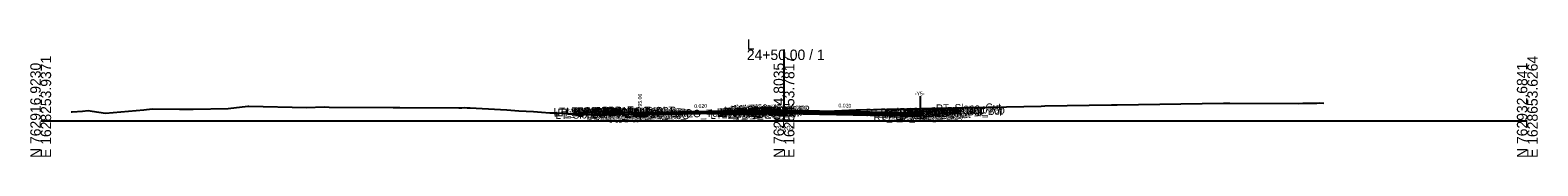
# Model space of a CAD drawing. Extents: x -26 to 4403, y -510 to 9556.
# Drawn here: x 997.2 to 1402.8, y 4490.3 to 4522 of the extents above; entities that cross this region are included whole.
import ezdxf

# ---------------------------------------------------------------- set-up
doc = ezdxf.new("R2010")
doc.units = 0
for name, color, linetype in [('Default', 7, 'Continuous'), ('Exist CMT Pavement', 7, 'Continuous'), ('Exist Cross Section Cell', 7, 'Continuous'), ('Exist XS Center Line Elevation Label', 7, 'Continuous'), ('Exist XS Ground Line', 7, 'Continuous'), ('Prop CMT Conc Surface', 7, 'Continuous'), ('Prop CMT Concrete Structures', 7, 'Continuous'), ('Prop CMT Pvmt Course 1', 7, 'Continuous'), ('Prop CMT Pvmt Course 1 CG', 7, 'Continuous'), ('Prop CMT Pvmt Course 1 Wedge', 7, 'Continuous'), ('Prop CMT Pvmt Course 2', 7, 'Continuous'), ('Prop CMT Pvmt Course 2 Wedge', 7, 'Continuous'), ('Prop CMT Pvmt Course 3', 7, 'Continuous'), ('Prop CMT Pvmt Course 3 Wedge', 7, 'Continuous'), ('Prop CMT Pvmt Surface', 7, 'Continuous'), ('Prop CMT Pvmt Wedge Surface 1', 7, 'Continuous'), ('Prop CMT Pvmt Wedge Surface 2', 7, 'Continuous'), ('Prop CMT Pvmt Wedge Surface 3', 7, 'Continuous'), ('Prop CMT Shear Line', 7, 'Continuous'), ('Prop CMT Subgrade Earthwork', 7, 'Continuous'), ('Prop XS Hydro Elevations', 7, 'Continuous'), ('Prop XS SE Text', 7, 'Continuous'), ('Scratch_Level_0', 7, 'Continuous')]:
    doc.layers.add(name, color=color, linetype=linetype)

msp = doc.modelspace()

# ---------------------------------------------------------------- linework, layer by layer
at = {"layer": 'Exist CMT Pavement'}
msp.add_lwpolyline([(1163.26, 4501.92), (1164.8, 4501.97), (1171.33, 4502.1), (1187.17, 4501.8), (1192, 4501.75)], dxfattribs=at)
at = {"layer": 'Exist Cross Section Cell'}
for p, q in [((1200, 4500), (1200, 4519.15)), ((1000, 4500), (1200, 4500)), ((1200, 4500), (1400, 4500))]:
    msp.add_line(p, q, dxfattribs=at)
at = {"layer": 'Exist XS Ground Line'}
msp.add_lwpolyline([(1008.18, 4502.4), (1008.49, 4502.41), (1011.23, 4502.63), (1012.8, 4502.75), (1013.86, 4502.58), (1017.47, 4502.04), (1027.71, 4502.96), (1030.01, 4503.17), (1037.35, 4503.15), (1041, 4503.16), (1050.42, 4503.33), (1055.71, 4503.89), (1056.03, 4503.89), (1071.5, 4503.54), (1076.31, 4503.74), (1077.61, 4503.65), (1094.85, 4503.6), (1095.34, 4503.6), (1096.65, 4503.59), (1112.49, 4503.52), (1113.32, 4503.52), (1114.01, 4503.53), (1114.71, 4503.46), (1115.54, 4503.44), (1123.71, 4503.03), (1125.38, 4502.99), (1128.66, 4502.66), (1132.64, 4502.47), (1134.75, 4502.3), (1137.01, 4502.16), (1138.89, 4502.17), (1143.69, 4501.9), (1146.02, 4501.9), (1148.59, 4501.59), (1149.36, 4501.47), (1164.8, 4501.97), (1171.33, 4502.1), (1187.17, 4501.8), (1193.05, 4501.74), (1193.4, 4501.75), (1194.22, 4501.79), (1195.2, 4501.83), (1200, 4502.04), (1219.45, 4502.91), (1220.62, 4502.93), (1238.54, 4503.31), (1241.19, 4503.37), (1269.18, 4503.97), (1270.19, 4503.99), (1288.15, 4504.26), (1289.61, 4504.27), (1318.28, 4504.7), (1319.07, 4504.71), (1319.98, 4504.72), (1338.5, 4504.67), (1339.62, 4504.7), (1340.53, 4504.72), (1343.37, 4504.73), (1344.14, 4504.79), (1345.26, 4504.75)], dxfattribs=at)
at = {"layer": 'Prop CMT Conc Surface'}
msp.add_lwpolyline([(1163.25, 4502.18), (1161.25, 4502.06)], dxfattribs=at)
at = {"layer": 'Prop CMT Concrete Structures'}
for p, q in [((1146.25, 4502.24), (1143.99, 4501.9)), ((1151.25, 4502.44), (1146.25, 4502.24)), ((1156.75, 4502.33), (1151.25, 4502.44)), ((1160.75, 4502.17), (1156.75, 4502.33)), ((1161.25, 4502.06), (1160.75, 4502.17))]:
    msp.add_line(p, q, dxfattribs=at)
for points in [[(1196, 4502.99), (1195.99, 4503.16), (1195.24, 4503.41), (1194, 4503.43), (1192.76, 4503.17), (1192.01, 4502.92), (1192, 4502.75)], [(1151.75, 4502.09), (1151.75, 4502.43)], [(1156.75, 4501.99), (1151.75, 4502.09)], [(1156.75, 4502.33), (1156.75, 4501.99)], [(1160.75, 4502.17), (1160.75, 4501.54), (1163.25, 4501.59)], [(1163.25, 4502.18), (1161.25, 4502.06)], [(1163.25, 4501.59), (1163.25, 4502.18)], [(1192, 4502.75), (1196, 4502.99)]]:
    msp.add_lwpolyline(points, dxfattribs=at)
at = {"layer": 'Prop CMT Pvmt Course 1'}
for points in [[(1192, 4502.75), (1163.25, 4502.18)], [(1163.25, 4502.05), (1192, 4502.63)], [(1163.25, 4502.18), (1163.25, 4501.93), (1163.25, 4501.93), (1163.25, 4502.05)], [(1192, 4502.75), (1196, 4502.99)], [(1192, 4502.5), (1192, 4502.75)], [(1192, 4502.5), (1192, 4502.75)], [(1196, 4502.74), (1192, 4502.5)], [(1192, 4502.63), (1192, 4502.5), (1192, 4502.5)], [(1196, 4502.99), (1196, 4502.74)], [(1196, 4502.99), (1236.75, 4502.18)], [(1196, 4502.74), (1196, 4502.99)], [(1236.75, 4501.93), (1196, 4502.74)], [(1236.75, 4502.18), (1236.75, 4501.93)]]:
    msp.add_lwpolyline(points, dxfattribs=at)
msp.add_lwpolyline([(1196, 4502.74), (1196, 4502.87), (1196, 4502.87), (1196, 4502.74)], close=True, dxfattribs=at)
at = {"layer": 'Prop CMT Pvmt Course 1 CG'}
for points in [[(1163.25, 4501.59), (1160.25, 4501.53), (1159.91, 4501.19)], [(1159.91, 4501.19), (1163.25, 4501.26)], [(1163.25, 4501.26), (1163.25, 4501.59)], [(1236.75, 4501.26), (1236.75, 4501.59)]]:
    msp.add_lwpolyline(points, dxfattribs=at)
at = {"layer": 'Prop CMT Pvmt Course 1 Wedge'}
for points in [[(1163.25, 4502.05), (1164.8, 4502.08), (1171.33, 4502.21), (1187.17, 4502.53), (1192, 4502.63)], [(1192, 4502.5), (1187.17, 4502.4), (1171.65, 4502.09), (1171.33, 4502.1), (1164.8, 4501.97), (1164.02, 4501.94), (1163.25, 4501.93)], [(1163.25, 4501.93), (1163.25, 4502.05)], [(1192, 4502.63), (1192, 4502.5)]]:
    msp.add_lwpolyline(points, dxfattribs=at)
at = {"layer": 'Prop CMT Pvmt Course 2'}
for points in [[(1163.25, 4501.59), (1163.25, 4501.59), (1163.25, 4501.93), (1163.25, 4501.93)], [(1163.25, 4501.93), (1163.25, 4501.59)], [(1192, 4502.5), (1196, 4502.74)], [(1192, 4502.17), (1192, 4502.5)], [(1196, 4502.41), (1192, 4502.17)], [(1196, 4502.74), (1196, 4502.41)], [(1196, 4502.41), (1196, 4502.74)], [(1196, 4502.74), (1236.75, 4501.93)], [(1236.75, 4501.59), (1196, 4502.41)], [(1236.75, 4501.93), (1236.75, 4501.59)]]:
    msp.add_lwpolyline(points, dxfattribs=at)
at = {"layer": 'Prop CMT Pvmt Course 2 Wedge'}
for points in [[(1163.25, 4501.93), (1164.02, 4501.94)], [(1164.02, 4501.94), (1163.25, 4501.92)], [(1163.25, 4501.92), (1163.25, 4501.93)], [(1171.65, 4502.09), (1187.17, 4502.4)], [(1192, 4502.17), (1187.17, 4502.07), (1180.18, 4501.93), (1171.65, 4502.09)], [(1187.17, 4502.4), (1192, 4502.5)], [(1192, 4502.5), (1192, 4502.17)]]:
    msp.add_lwpolyline(points, dxfattribs=at)
at = {"layer": 'Prop CMT Pvmt Course 3'}
for points in [[(1163.25, 4501.59), (1163.25, 4501.59), (1163.25, 4501.26), (1163.25, 4501.26)], [(1163.25, 4501.26), (1163.25, 4501.59)], [(1192, 4502.17), (1196, 4502.41)], [(1192, 4501.83), (1192, 4502.17)], [(1196, 4502.07), (1192, 4501.83)], [(1196, 4502.41), (1196, 4502.07)], [(1196, 4502.41), (1236.75, 4501.59)], [(1196, 4502.07), (1196, 4502.41)], [(1236.75, 4501.26), (1196, 4502.07)], [(1236.75, 4501.59), (1236.75, 4501.26)]]:
    msp.add_lwpolyline(points, dxfattribs=at)
at = {"layer": 'Prop CMT Pvmt Course 3 Wedge'}
for points in [[(1180.19, 4501.93), (1187.17, 4502.07)], [(1192, 4501.73), (1187.17, 4501.8), (1180.19, 4501.93)], [(1187.17, 4502.07), (1192, 4502.17)], [(1192, 4502.17), (1192, 4501.73)]]:
    msp.add_lwpolyline(points, dxfattribs=at)
at = {"layer": 'Prop CMT Pvmt Surface'}
for points in [[(1192, 4502.75), (1163.25, 4502.18)], [(1192, 4502.75), (1196, 4502.99)], [(1196, 4502.99), (1236.75, 4502.18)]]:
    msp.add_lwpolyline(points, dxfattribs=at)
at = {"layer": 'Prop CMT Pvmt Wedge Surface 1'}
for points in [[(1192, 4502.63), (1163.25, 4502.05)], [(1163.25, 4501.93), (1163.25, 4502.18)], [(1163.25, 4502.05), (1163.25, 4501.93), (1163.25, 4501.93)], [(1192, 4502.75), (1192, 4502.5), (1192, 4502.5), (1192, 4502.63)]]:
    msp.add_lwpolyline(points, dxfattribs=at)
at = {"layer": 'Prop CMT Pvmt Wedge Surface 2'}
for points in [[(1192, 4502.5), (1163.25, 4501.93)], [(1163.25, 4501.93), (1163.25, 4502.18)], [(1192, 4502.75), (1192, 4502.5)]]:
    msp.add_lwpolyline(points, dxfattribs=at)
at = {"layer": 'Prop CMT Pvmt Wedge Surface 3'}
for points in [[(1163.25, 4501.59), (1163.25, 4502.18)], [(1192, 4502.17), (1163.25, 4501.59)], [(1192, 4502.75), (1192, 4502.17)]]:
    msp.add_lwpolyline(points, dxfattribs=at)
at = {"layer": 'Prop CMT Shear Line'}
msp.add_line((1236.75, 4500.37), (1236.75, 4506.64), dxfattribs=at)
at = {"layer": 'Prop CMT Subgrade Earthwork'}
for p, q in [((1236.75, 4501.26), (1236.75, 4503.27)), ((1192, 4501.75), (1192, 4501.83))]:
    msp.add_line(p, q, dxfattribs=at)
for points in [[(1163.25, 4501.26), (1159.91, 4501.19), (1158.86, 4502.24)], [(1163.25, 4501.26), (1163.26, 4501.92)], [(1163.25, 4501.26), (1163.25, 4501.26)], [(1192, 4501.83), (1196, 4502.07)], [(1196, 4502.07), (1236.75, 4501.26)]]:
    msp.add_lwpolyline(points, dxfattribs=at)

# ---------------------------------------------------------------- texts
at = {"layer": 'Default'}
msp.add_text('-', height=0.0001, dxfattribs=at).set_placement((1000, 4500))
at = {"layer": 'Exist Cross Section Cell'}
for s, p in [('24+50.00 / 1', (1190, 4516.35)), ('L', (1190, 4519.15))]:
    msp.add_text(s, height=2.8, dxfattribs=at).set_placement(p)
for s, p in [('N 762916.9230', (1000, 4490)), ('E 1628253.9371', (1002.8, 4490)), ('N 762924.8035', (1200, 4490)), ('E 1628453.7817', (1202.8, 4490)), ('N 762932.6841', (1400, 4490)), ('E 1628653.6264', (1402.8, 4490))]:
    msp.add_text(s, height=2.8, rotation=90, dxfattribs=at).set_placement(p)
at = {"layer": 'Exist XS Center Line Elevation Label'}
msp.add_text('795.04', height=1.2, dxfattribs=at).set_placement((1197.48, 4497.44))
at = {"layer": 'Prop XS Hydro Elevations'}
for s, rotation, p in [('-Y5-', 360, (1235.23, 4506.81)), ('795.06', 90, (1161.75, 4503.06))]:
    msp.add_text(s, height=1, rotation=rotation, dxfattribs=at).set_placement(p)
at = {"layer": 'Prop XS SE Text'}
for s, rotation, p in [('15.00%', 8.5308, (1141.27, 4501.84)), ('4.00%', 2.2906, (1146.99, 4502.49)), ('2.00%', 358.8542, (1152.4, 4502.61)), ('4.00%', 357.7094, (1156.62, 4502.64)), ('0.020', 1.1458, (1175.86, 4503.43)), ('0.020', 358.8542, (1214.65, 4503.62))]:
    msp.add_text(s, height=1, rotation=rotation, dxfattribs=at).set_placement(p)
at = {"layer": 'Scratch_Level_0'}
for s, p in [('LT_SDWK_Out_Top', (1138.01, 4501.47)), ('LT_SDWK_Out_Bot', (1138.04, 4501.14)), ('LT_Sub_Trench_Out_DLT', (1139.09, 4501.21)), ('LT_CSLP_Pnt', (1141.45, 4501.55)), ('24+50.00', (1143.18, 4501.17)), ('LT_SDWK_In_Top', (1144.63, 4501.4)), ('LT_SDWK_In_Bot', (1144.66, 4501.07)), ('24+50.00', (1144.76, 4501.61)), ('LT_PV_Sub_Tie_Out', (1148.23, 4500.62)), ('LT_CG_Top_Face', (1148.53, 4501.3)), ('LT_CG_Top_BOC', (1149.05, 4501.32)), ('LT_CG_Top_Gut', (1149.51, 4500.82)), ('LT_PV_OEEOP_EG', (1150.82, 4500.67)), ('LT_PV2_OEEOP', (1152.58, 4500.71)), ('LT_PV1_OEEOP', (1153.15, 4500.85)), ('LT_PV2_OEOT', (1153.44, 4500.73)), ('24+50.00', (1153.66, 4501.43)), ('LT_PV1_OEOT', (1154.01, 4500.99)), ('24+50.00', (1155.31, 4500.97)), ('LT_PV_EG_TestPt', (1164.06, 4500.71)), ('LT_PV2_IEEOP', (1181.97, 4501.3)), ('LT_PV3_IEEOP', (1181.97, 4500.97)), ('LT_PV1_IEEOP', (1182.54, 4501.44)), ('LT_PV2_PGL1', (1182.9, 4501.32)), ('LT_PV3_PGL1', (1182.9, 4500.98)), ('LT_PV2_PGL', (1183.23, 4501.33)), ('LT_PV3_PGL', (1183.23, 4500.99)), ('LT_PV1_PGL', (1183.8, 4501.59)), ('MI_Face In', (1183.92, 4501.76)), ('RT_Sub_OEEOP', (1185.19, 4500.86)), ('24+50.00', (1185.27, 4501.7)), ('RT_PV2_OEEOP', (1185.28, 4501.53)), ('RT_PV3_OEEOP', (1185.28, 4501.19)), ('24+50.00', (1185.68, 4501.92)), ('MI_Top In', (1185.63, 4502.02)), ('RT_PV1_OEEOP', (1185.85, 4501.66)), ('RT_PV2_IEEOP', (1185.93, 4501.54)), ('MI_Face Out', (1186.28, 4501.96)), ('MI_Top Out', (1186.49, 4502.23)), ('RT_PV1_IEEOP', (1186.49, 4501.68)), ('RT_PV2_PGL1', (1186.86, 4501.56)), ('RT_PV3_PGL1', (1186.86, 4501.22)), ('MI_Crown', (1187.09, 4502.29)), ('RT_PV2_PGL', (1187.19, 4501.56)), ('RT_PV4_PGL', (1187.19, 4500.9)), ('MI_Bot Out', (1187.28, 4501.82)), ('RT_PV1_PGL', (1187.75, 4501.83)), ('24+50.00', (1188.15, 4502.28)), ('RT_Sub_Trench_Out_DLT', (1222.04, 4501.21)), ('RT_CG_Top_Face', (1225.99, 4501.3)), ('RT_PV2_OEOT', (1226.9, 4500.73)), ('RT_CG_Top_Gut', (1226.96, 4500.82)), ('RT_PV1_OEOT', (1227.46, 4500.99)), ('RT_CG_Top_BOC', (1227.51, 4501.32)), ('24+50.00', (1231.05, 4500.98)), ('RT_SDWK_In_Top', (1231.08, 4501.4)), ('RT_SDWK_In_Bot', (1231.12, 4501.07)), ('24+50.00', (1233.12, 4501.43)), ('RT_SDWK_Out_Top', (1234.46, 4501.47)), ('RT_SDWK_Out_Bot', (1234.49, 4501.14)), ('RT_Shld_O', (1240.81, 4501.59)), ('RT_Slope_Cut', (1240.88, 4502.38)), ('CSLP_Pnt', (1241.64, 4501.6)), ('24+50.00', (1241.7, 4501.61)), ('LT_Slope_Fill', (1138.54, 4500.47)), ('LT_CG1_Shelf_Out', (1146.82, 4500.26)), ('LT_CG_Bot_BOC', (1149.09, 4500.31)), ('LT_Sub_OEOP', (1150.04, 4499.99)), ('LT_Sub_OEOT_CG', (1150.64, 4500.01)), ('LT_Sub_OEEOP', (1152.48, 4500.04)), ('LT_PV3_OEEOP', (1152.58, 4500.38)), ('LT_CG_Bot_IE', (1153.19, 4500.39)), ('LT_Sub_OEOT', (1153.35, 4500.06)), ('LT_PV3_OEOT', (1153.44, 4500.4)), ('LT_PV_IEEOP_EG', (1180.21, 4500.5)), ('LT_PV4_PGL', (1183.23, 4500.66)), ('RT_Sub_OEOT_CG', (1224.1, 4500.01)), ('RT_CG1_Shelf_Out', (1226.28, 4500.26)), ('RT_CG_Bot_IE', (1226.64, 4500.39)), ('RT_Sub_OEOT', (1226.8, 4500.06)), ('RT_PV3_OEOT', (1226.9, 4500.39)), ('RT_CG_Bot_BOC', (1227.54, 4500.31)), ('RT_Sub_OEOP', (1230.18, 4499.99))]:
    msp.add_text(s, height=2, rotation=1.1458, dxfattribs=at).set_placement(p)

doc.saveas('drawing.dxf')
